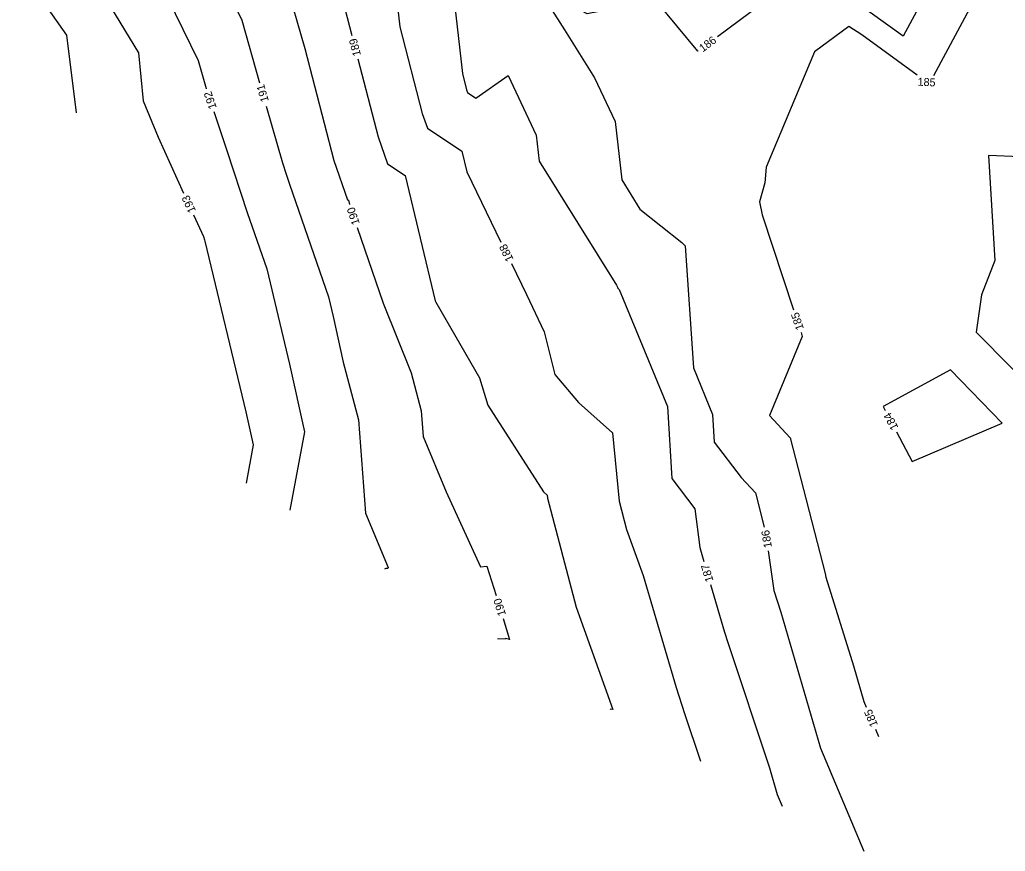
# Model space of a CAD drawing. Extents: x 2086416 to 2115205, y 575507 to 632762.
# Drawn here: x 2110178.9 to 2110425.2, y 581656.9 to 581864.8 of the extents above; entities that cross this region are included whole.
import ezdxf

# ---------------------------------------------------------------- set-up
doc = ezdxf.new("R2010")
doc.units = 0
for name, color, linetype in [('DTM Contours Major', 7, 'Continuous'), ('DTM Contours Major Text', 7, 'Continuous'), ('DTM Contours Minor', 7, 'Continuous'), ('DTM Contours Minor Text', 7, 'Continuous')]:
    doc.layers.add(name, color=color, linetype=linetype)

msp = doc.modelspace()

# ---------------------------------------------------------------- linework, layer by layer
at = {"layer": 'DTM Contours Major'}
for points in [[(2110369.37, 581922.2), (2110372.5, 581918.84), (2110375.41, 581915.72), (2110377.65, 581904.64), (2110390.4, 581892.7), (2110397.79, 581891.94), (2110416.83, 581876.68), (2110419.88, 581874.24), (2110407.25, 581850.79)], [(2110253.22, 581913.88), (2110242.42, 581880.48), (2110245.25, 581874.66), (2110250.14, 581857.58), (2110257.38, 581829.58), (2110260.82, 581819.81), (2110261.06, 581819.65), (2110261.31, 581818.59)], [(2110403.16, 581850.97), (2110389.35, 581861.02), (2110386.08, 581863.1), (2110377.56, 581856.78), (2110365.48, 581827.95), (2110365.13, 581823.98), (2110363.82, 581819.31), (2110364.47, 581816.05), (2110372.29, 581792.29)], [(2110263.2, 581812.89), (2110269.7, 581793.97), (2110276.69, 581776.53), (2110279.24, 581766.99), (2110279.72, 581760.61), (2110285.47, 581746.75), (2110294.07, 581728.05), (2110295.66, 581728.24), (2110297.93, 581720.83)], [(2110374.17, 581786.59), (2110374.48, 581785.64), (2110366.28, 581765.86), (2110371.48, 581760.29), (2110380.21, 581726.38), (2110380.34, 581725.48), (2110387.29, 581703.26), (2110389.89, 581694.37), (2110390.47, 581692.99)], [(2110299.7, 581715.1), (2110301.31, 581709.84), (2110300.26, 581710.15), (2110300.23, 581709.91), (2110298.48, 581710.03), (2110298.27, 581709.94)], [(2110392.78, 581687.45), (2110393.54, 581685.63)]]:
    msp.add_lwpolyline(points, dxfattribs=at)
at = {"layer": 'DTM Contours Minor'}
for points in [[(2110301.63, 581975.45), (2110302.04, 581974.77), (2110310.59, 581959.81), (2110285.87, 581958.31), (2110269.33, 581957.31), (2110265.53, 581957.76), (2110258.51, 581958.57), (2110218.92, 581909.52), (2110215.63, 581898.75), (2110210.19, 581881.92), (2110223.48, 581854.62), (2110225.48, 581847.63), (2110225.52, 581847.51)], [(2110310.4, 581975.13), (2110311.78, 581972.92), (2110319.5, 581959.4), (2110319.67, 581959.11), (2110326.46, 581952.81), (2110336.26, 581932.33), (2110337.91, 581930.13), (2110342.94, 581918.36), (2110327.45, 581919.35), (2110326.2, 581920.21), (2110297.45, 581918.49), (2110279.39, 581918.55), (2110267.52, 581916.71), (2110261.26, 581895.57), (2110257.09, 581881.5), (2110257.62, 581880.73), (2110258.31, 581874.72), (2110261.9, 581860.82)], [(2110277.9, 581972.3), (2110273.06, 581972), (2110267.58, 581972.65), (2110257.47, 581973.82), (2110200.42, 581903.14), (2110195.69, 581887.62), (2110194.08, 581882.65), (2110199.28, 581871.96), (2110208.59, 581856.5), (2110209.7, 581844.49), (2110213.48, 581835.41), (2110219.86, 581821.45)], [(2110305.75, 581973.35), (2110317.27, 581953.18), (2110317.3, 581953.14), (2110318.49, 581952.03), (2110321.38, 581945.99), (2110310.24, 581946.03), (2110302.75, 581944.87), (2110274.84, 581943.18), (2110265.6, 581942.62), (2110263.47, 581942.87), (2110259.55, 581943.32), (2110237.41, 581915.9), (2110235.58, 581909.87), (2110226.31, 581881.2), (2110234.36, 581864.64), (2110238.85, 581848.99)], [(2110328.29, 581963.38), (2110338.41, 581953.97), (2110340.59, 581949.41), (2110349.17, 581938.01), (2110353.6, 581927.66), (2110366.24, 581914.12), (2110368.17, 581912.04), (2110373.36, 581886.45), (2110376.29, 581883.71), (2110395.58, 581881.74), (2110404.88, 581874.28), (2110406.37, 581873.09), (2110399.68, 581860.65), (2110391.46, 581866.63), (2110375.29, 581876.92), (2110353.26, 581860.55)], [(2110347.71, 581918.62), (2110353.65, 581904.72), (2110353.7, 581904.68), (2110353.7, 581904.67), (2110353.73, 581904.55), (2110353.54, 581904.51), (2110353.43, 581904.57), (2110316.59, 581906.92), (2110313.59, 581908.97), (2110276.62, 581906.77), (2110270.04, 581884.58), (2110271.75, 581882.11), (2110273.92, 581863.02), (2110279.51, 581841.39), (2110280.82, 581837.67), (2110289.39, 581831.97), (2110290.63, 581826.76), (2110299.16, 581809.22)], [(2110185.22, 581900.84), (2110181.93, 581896.76), (2110178.88, 581886.78), (2110181.8, 581873.46), (2110190.57, 581860.89), (2110193.02, 581841.51)], [(2110288.13, 581896.97), (2110285.71, 581896.82), (2110283, 581887.65), (2110285.87, 581883.5), (2110289.54, 581851.33), (2110290.58, 581847.3), (2110290.82, 581846.6), (2110292.92, 581845.21), (2110300.94, 581850.81), (2110307.98, 581835.94), (2110308.72, 581829.44), (2110328.04, 581798.41), (2110328.28, 581797.91), (2110328.33, 581797.81), (2110328.36, 581797.69), (2110328.67, 581797.32), (2110340.79, 581768.09), (2110341.88, 581750.11), (2110347.64, 581742.54), (2110348.83, 581732.84), (2110349.85, 581729.37)], [(2110348.44, 581856.97), (2110348.37, 581856.91), (2110337.84, 581869.61), (2110320.7, 581866.27), (2110308.32, 581872.89), (2110315.01, 581862.24), (2110322.51, 581850.28), (2110327.68, 581839.37), (2110329.34, 581824.75), (2110333.87, 581817.46), (2110344.38, 581809.08), (2110345.17, 581808.24), (2110347.25, 581777.74), (2110352.06, 581766.14), (2110352.48, 581759.21), (2110359.23, 581750.34), (2110362.78, 581746.53), (2110364.99, 581737.98)], [(2110263.4, 581855.01), (2110268.44, 581835.49), (2110270.82, 581828.74), (2110275.22, 581825.81), (2110282.69, 581794.52), (2110282.77, 581794.34), (2110282.85, 581794.18), (2110293.82, 581775.31), (2110295.89, 581768.48), (2110309.77, 581746.75), (2110310.69, 581745.93), (2110310.76, 581745.16), (2110317.97, 581717.95), (2110327.13, 581692.38), (2110326.53, 581692.42), (2110326.49, 581692.4)], [(2110227.42, 581841.82), (2110230.67, 581832.1), (2110235.74, 581816.62), (2110240.62, 581802.48), (2110246.33, 581778.69), (2110250.03, 581761.79), (2110246.42, 581742.17)], [(2110240.5, 581843.22), (2110244.57, 581828.98), (2110245.5, 581826.22), (2110246.4, 581823.47), (2110256.06, 581795.5), (2110257.23, 581790.62), (2110259.73, 581779.19), (2110263.59, 581764.77), (2110265.33, 581741.41), (2110270.94, 581727.87), (2110270.91, 581727.61), (2110270.43, 581727.64), (2110270.06, 581727.47)], [(2110512.45, 581799.94), (2110493.85, 581798.28), (2110491.61, 581798.98), (2110486.39, 581800.61), (2110477.44, 581810.98), (2110475.99, 581811.48), (2110461.73, 581822.53), (2110445.25, 581825.89), (2110436.87, 581830.21), (2110421.03, 581830.82), (2110422.59, 581804.61), (2110419.24, 581796.01), (2110417.96, 581786.65), (2110435.66, 581768.75), (2110437.3, 581769.68), (2110441.51, 581762.84), (2110427.74, 581762.65), (2110429.81, 581758.8)], [(2110222.35, 581815.99), (2110224.8, 581810.63), (2110225.08, 581809.76), (2110225.19, 581809.45), (2110235.43, 581766.76), (2110237.23, 581758.53), (2110235.48, 581748.98)], [(2110301.78, 581803.83), (2110305.53, 581796.12), (2110309.95, 581786.81), (2110312.65, 581776.15), (2110318.53, 581769.15), (2110327.05, 581761.53), (2110328.7, 581744.46), (2110330.58, 581737.39), (2110334.7, 581725.87), (2110342.92, 581697.83), (2110345.05, 581691.4), (2110349, 581679.45)], [(2110424.41, 581763.97), (2110411.51, 581777.24), (2110394.67, 581768.08), (2110395.2, 581767.07)], [(2110398.01, 581761.76), (2110401.92, 581754.37), (2110424.41, 581763.97)], [(2110365.97, 581732.06), (2110367.4, 581722.15), (2110369.12, 581716.67), (2110379.05, 581682.73), (2110389.83, 581656.93)], [(2110351.54, 581723.61), (2110355.03, 581711.72), (2110355.88, 581709.13), (2110366.25, 581677.78), (2110368.21, 581671.09), (2110369.42, 581668.18)]]:
    msp.add_lwpolyline(points, dxfattribs=at)

# ---------------------------------------------------------------- texts
at = {"layer": 'DTM Contours Major Text'}
for s, rotation, p in [('185', 357.4395, (2110403.27, 581848.31)), ('190', 108.3676, (2110263.89, 581813.89)), ('185', 108.2264, (2110374.89, 581787.59)), ('190', 107.0941, (2110300.44, 581716.08)), ('185', 112.6798, (2110393.42, 581688.51))]:
    msp.add_text(s, height=2, rotation=rotation, dxfattribs=at).set_placement(p)
at = {"layer": 'DTM Contours Minor Text'}
for s, rotation, p in [('189', 104.4886, (2110264.19, 581855.96)), ('186', 36.605, (2110349.62, 581856.6)), ('192', 108.4618, (2110228.14, 581842.82)), ('191', 105.9786, (2110241.17, 581844.52)), ('193', 114.5362, (2110222.96, 581817.06)), ('188', 115.93, (2110302.36, 581804.91)), ('184', 117.8676, (2110398.55, 581762.87)), ('186', 99.4693, (2110366.9, 581732.95)), ('187', 106.3462, (2110352.3, 581724.58))]:
    msp.add_text(s, height=2, rotation=rotation, dxfattribs=at).set_placement(p)

doc.saveas('drawing.dxf')
